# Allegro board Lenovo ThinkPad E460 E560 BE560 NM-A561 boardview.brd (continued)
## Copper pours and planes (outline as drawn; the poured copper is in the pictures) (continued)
N48440766 on BOTTOM (solid shape): 135.41,48.49 136.58,48.49 136.73,48.34 136.73,47.61 136.63,47.51 134.02,47.51 133.79,47.74 133.79,48.53 133.91,48.66 135.25,48.66
N48440774 on BOTTOM (solid shape): 140.04,47.94 140.04,47.03 139.86,46.85 139.1,46.85 139.05,46.9 139.05,47.16 139.78,47.89 139.78,47.97 139.83,48.02 139.96,48.02
N48440814 on TOP (solid shape): 137.37,54.7 137.37,53.02 137.27,52.92 136.53,52.92 136.43,53.02 136.43,54.65 136.53,54.75 137.32,54.75
N55632055 on BOTTOM (solid shape): 214.13,156.45 214.13,156.1 214.23,156 214.23,154.98 214.18,154.93 213.26,154.93 213.21,154.98 213.21,155.97 213.39,156.15 213.39,156.45 213.49,156.55 214.03,156.55
N55632901 on BOTTOM (solid shape): 215.07,156.43 215.07,155.03 214.99,154.95 214.51,154.95 214.46,155.01 214.46,156.02 214.31,156.17 214.31,156.45 214.38,156.53 214.97,156.53
N55637104 on BOTTOM (solid shape): 216.29,155.84 216.29,154.98 215.83,154.52 215.3,154.52 215.17,154.65 215.17,154.73 215.47,155.03 215.47,155.61 215.78,155.92 216.21,155.92
N55638710 on BOTTOM (solid shape): 212.25,156.68 212.25,155.03 212.15,154.93 211.66,154.93 211.59,155.01 211.59,156.63 211.72,156.76 212.17,156.76
N56243451 on BOTTOM (solid shape): 234.51,160.72 234.83,160.54 235.15,160.72 237.39,160.72 237.62,160.5 237.62,158.54 237.26,158.18 231.78,158.18 231.63,158.33 231.63,160.52 231.83,160.72
N56799483 on BOTTOM (solid shape): 38.44,113.98 38.44,112.1 38.28,111.95 37.32,111.95 37.19,111.83 35.92,111.83 35.67,112.08 35.67,112.69 37.75,112.69 37.75,113.2 36,113.2 36,112.69 35.67,112.69 35.67,113.93 35.85,114.11 38.31,114.11
N56799483 on BOTTOM (solid shape): 38.54,121.58 38.54,119.29 38.44,119.19 38.12,119.19 37.82,119.5 35.79,119.5 35.59,119.7 35.59,120.28 37.83,120.28 37.83,120.84 35.9,120.84 35.9,120.28 35.59,120.28 35.59,121.58 35.79,121.78 38.33,121.78
N56799483 on TOP: 38.72,112.23 38.47,111.99 36.32,111.99 36.12,112.18 36.12,121.1 36.91,121.88 38.49,121.88 38.72,121.66
N57740748 on BOTTOM (solid shape): 116.85,186.04 116.85,183.66 116.72,183.53 116.64,183.53 116.59,183.58 116.59,184.82 116.31,185.1 115.96,185.1 115.78,184.93 115.78,183.73 115.47,183.43 114.61,183.43 114.51,183.53 114.51,186.17 114.66,186.32 116.57,186.32
N58156905 on BOTTOM (solid shape): 225.86,162.57 225.86,161.61 225.74,161.48 224.9,161.48 224.75,161.63 224.75,162.55 224.85,162.65 225.79,162.65
N59027809 on BOTTOM (solid shape): 239.2,175.66 239.2,173.98 239.07,173.85 233.97,173.85 233.89,173.93 233.89,175.43 234.19,175.73 239.12,175.73
N59815990 on TOP: 166.3,124.25 166.66,124.25 171.16,128.75 172.41,128.75 173.89,130.24 175.09,130.24 175.65,129.68 175.65,128.21 175.06,127.62 173.26,127.62 167.04,121.4 166.5,121.4 166.17,121.73 166.17,122.47 166.3,122.59 166.3,123.36 166.05,123.61 166.05,123.99
N60939795 on BOTTOM (solid shape): 168.55,6.86 168.55,6.07 168.97,5.65 169.88,5.65 170.06,5.48 170.06,4.2 169.79,3.93 169.79,3.21 169.72,3.14 169.22,3.14 169.09,3.27 169.09,5.04 168.31,5.83 168.31,6.85 168.36,6.9 168.51,6.9
N60939813 on TOP (solid shape): 165.06,10.45 165.06,9.49 164.95,9.39 163.15,9.39 163.05,9.49 163.05,10.43 163.18,10.56 164.95,10.56
N63295136 on TOP (solid shape): 165.04,8.21 165.04,7.26 164.9,7.13 163.12,7.13 162.97,7.28 162.97,8.19 163.12,8.35 164.9,8.35
N63300161 on TOP (solid shape): 192.31,4.74 192.31,2.94 192.16,2.78 191.52,2.78 191.37,2.94 191.37,4.69 191.47,4.79 192.26,4.79
N63300165 on TOP (solid shape): 194.06,7.94 194.06,7.18 193.86,6.97 191.37,6.97 191.29,7.05 191.29,8.02 191.42,8.14 193.86,8.14
N68513948 on TOP: 195.97,70.32 198.25,70.32 198.56,70.02 198.56,68.14 198.3,67.88 195.59,67.88 195.48,67.98 195.48,69.84
N69409003 on BOTTOM (solid shape): 35.17,83.1 35.17,80.94 35.05,80.81 30.98,80.81 30.73,81.07 30.73,82.59 30.85,82.72 31.04,82.72 32,83.67 34.6,83.67
N69409003 on TOP: 29.39,86.43 29.7,86.43 29.83,86.3 29.83,85.49 30.16,85.16 31.55,85.16 32.99,83.71 33.01,83.71 33.06,83.67 34.66,83.67 34.82,83.51 34.82,82.08 34.24,81.5 31.71,81.5 30.87,82.34 30.87,84.09 30.74,84.22 30.51,84.22 29.34,85.38 29.34,86.37
N71613177 on TOP (solid shape): 78.13,132.44 78.13,132.31 78.75,131.69 78.73,131.65 78.79,131.25 79.17,131.15 79.21,131.16 79.3,131.07 79.3,129.77 79.24,129.71 78.73,129.71 78.61,129.83 78.61,130.41 78.67,130.47 78.67,130.95 78.61,131.01 78.6,131.01 78.54,131.1 78.45,131.17 78.44,131.17 78,131.61 77.3,131.61 77.15,131.77 77.15,132.58 77.21,132.64 77.92,132.64
N71773779 on TOP: 220.25,10.99 221.42,10.99 221.85,11.42 221.85,15 221.57,15.28 220.2,15.28 220.19,15.27 220.06,15.27 219.97,15.18 219.97,11.27

Small or netless copper shapes (teardrops, artwork), in the pictures only: 20 on TOP, 19 on BOTTOM, 1 on VCC

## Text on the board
Ref Des/Silkscreen Bottom: KB
Ref Des/Silkscreen Top: M2X5
BODY_CENTER: POWER
User.45: FIGURE | SIZE | 8.0 | 9.0 | 10.0 | 22.0 | 24.0 | 28.0 | 35.0 | 39.0 | 87.0 | 91.0 | 124.0 | 43.0 | 47.0 | 55.0 | 63.0 | 39.0x28.0 | 63.0x35.0 | 75.0x31.0 | 102.0x24.0 | 102.0x28.0 | 102.0x31.0 | 110.0x91.0 | DRILL CHART: TOP to BOTTOM | ALL UNITS ARE IN MILS | PLATED | NON-PLATED | QTY | 1053 | 117 | 274 | 5565 | 22 | 19 | 11 | 18 | 7 | 8 | 4 | 2 | 6 | 17 | 3 | 1 | 10
